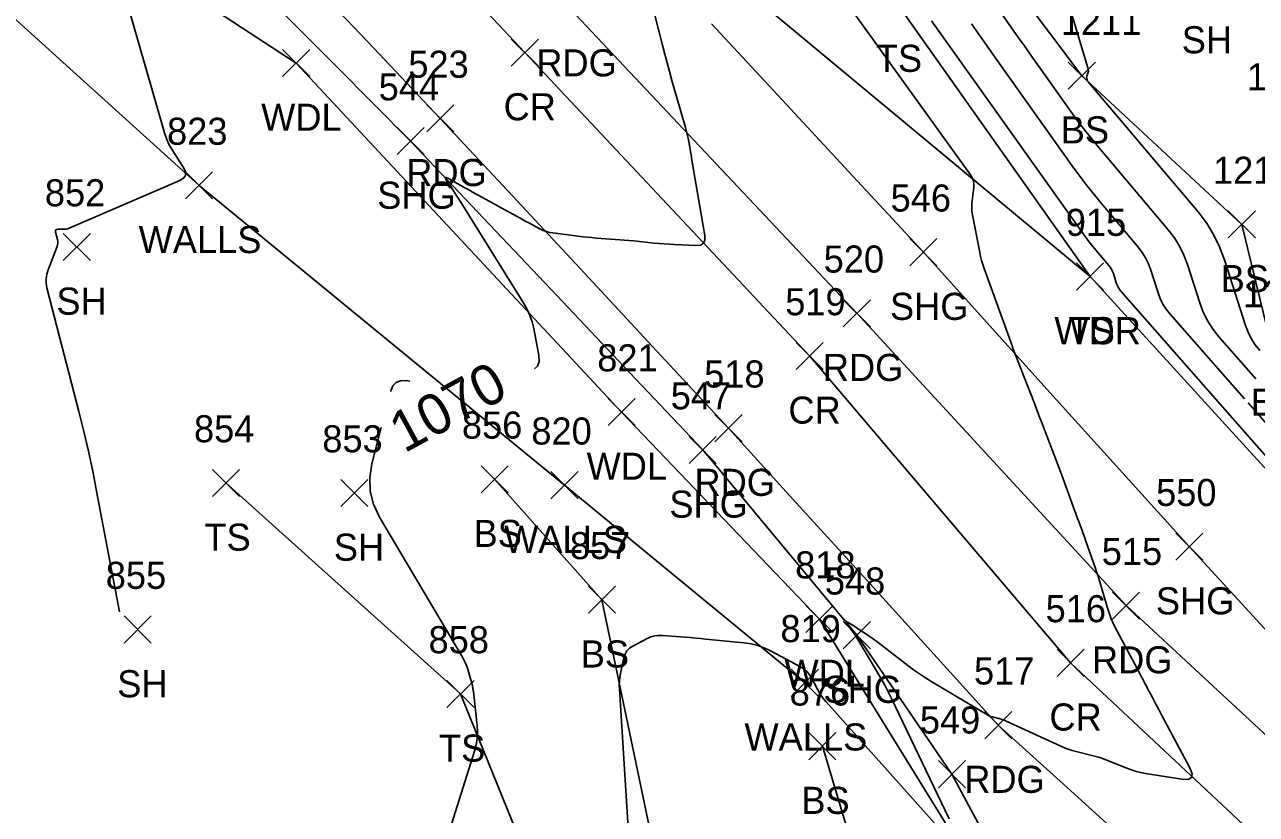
# Model space of a CAD drawing. Extents: x 1592612 to 1596497, y 111838 to 113741.
# Drawn here: x 1592719.3 to 1592810.3, y 113490.1 to 113548.4 of the extents above; entities that cross this region are included whole.
import ezdxf

# ---------------------------------------------------------------- set-up
doc = ezdxf.new("R2010")
doc.units = 0
for name, color, linetype in [('L_A', 7, 'Continuous'), ('L_I', 7, 'Continuous'), ('L_TIC', 7, 'Continuous'), ('LAWA', 7, 'Continuous'), ('LELB', 7, 'Continuous'), ('LSOGCMA', 7, 'Continuous'), ('LSOGCMA_T', 7, 'Continuous'), ('LSOGCMI', 7, 'Continuous'), ('LWS', 7, 'Continuous'), ('P_A', 7, 'Continuous'), ('P_I', 7, 'Continuous'), ('P_TIC', 7, 'Continuous'), ('PEU', 7, 'Continuous'), ('PRC', 7, 'Continuous'), ('PSU', 7, 'Continuous')]:
    doc.layers.add(name, color=color, linetype=linetype)

msp = doc.modelspace()

# ---------------------------------------------------------------- linework, layer by layer
at = {"layer": 'L_TIC'}
for points in [[(1592738.369, 113544.558), (1592740.369, 113546.558)], [(1592740.369, 113544.558), (1592738.369, 113546.558)], [(1592796.4, 113543.62), (1592798.4, 113545.62)], [(1592798.4, 113543.62), (1592796.4, 113545.62)], [(1592731.196, 113535.522), (1592733.196, 113537.522)], [(1592733.196, 113535.522), (1592731.196, 113537.522)], [(1592808.213, 113532.643), (1592810.213, 113534.643)], [(1592810.213, 113532.643), (1592808.213, 113534.643)], [(1592722.173, 113530.98), (1592724.173, 113532.98)], [(1592724.173, 113530.98), (1592722.173, 113532.98)], [(1592797.01, 113528.796), (1592799.01, 113530.796)], [(1592799.01, 113528.796), (1592797.01, 113530.796)], [(1592797.01, 113528.796), (1592799.01, 113530.796)], [(1592799.01, 113528.796), (1592797.01, 113530.796)], [(1592762.403, 113518.793), (1592764.403, 113520.793)], [(1592764.403, 113518.793), (1592762.403, 113520.793)], [(1592753.03, 113513.829), (1592755.03, 113515.829)], [(1592755.03, 113513.829), (1592753.03, 113515.829)], [(1592733.185, 113513.556), (1592735.185, 113515.556)], [(1592735.185, 113513.556), (1592733.185, 113515.556)], [(1592758.191, 113513.391), (1592760.191, 113515.391)], [(1592760.191, 113513.391), (1592758.191, 113515.391)], [(1592742.664, 113512.815), (1592744.664, 113514.815)], [(1592744.664, 113512.815), (1592742.664, 113514.815)], [(1592760.95, 113504.931), (1592762.95, 113506.931)], [(1592762.95, 113504.931), (1592760.95, 113506.931)], [(1592777.021, 113503.51), (1592779.021, 113505.51)], [(1592779.021, 113503.51), (1592777.021, 113505.51)], [(1592726.669, 113502.735), (1592728.669, 113504.735)], [(1592728.669, 113502.735), (1592726.669, 113504.735)], [(1592775.94, 113498.802), (1592777.94, 113500.802)], [(1592777.94, 113498.802), (1592775.94, 113500.802)], [(1592750.511, 113497.983), (1592752.511, 113499.983)], [(1592752.511, 113497.983), (1592750.511, 113499.983)], [(1592777.24, 113494.122), (1592779.24, 113496.122)], [(1592779.24, 113494.122), (1592777.24, 113496.122)]]:
    msp.add_lwpolyline(points, dxfattribs=at)
at = {"layer": 'LAWA'}
for points in [[(1592820.851, 113504.774), (1592798.01, 113529.796), (1592767.974, 113554.756), (1592744.7, 113575.871), (1592731.754, 113590.187), (1592719.52, 113602.847), (1592702.926, 113618.445), (1592691.78, 113628.612), (1592676.133, 113644.708)], [(1592820.49, 113445.204), (1592799.578, 113454.201), (1592791.672, 113482.437), (1592778.021, 113504.51), (1592763.403, 113519.793), (1592739.369, 113545.558), (1592709.175, 113565.248), (1592691.74, 113580.372), (1592683.654, 113590.995), (1592666.454, 113606.066), (1592652.114, 113621.499)]]:
    msp.add_lwpolyline(points, dxfattribs=at)
at = {"layer": 'LELB'}
for points in [[(1592701.588, 113659.774), (1592726.097, 113635.895), (1592737.453, 113625.119), (1592757.272, 113620.552), (1592765.525, 113604.487), (1592785.217, 113593.362), (1592785.143, 113579.955), (1592783.097, 113567.939), (1592785.828, 113560.008), (1592797.4, 113544.62), (1592809.213, 113533.643), (1592811.425, 113524.524), (1592820.841, 113522.69), (1592826.429, 113512.914)], [(1592798.011, 113529.796), (1592783.774, 113549.905), (1592769.456, 113556.017), (1592755.948, 113571.656), (1592745.631, 113578.976), (1592738.042, 113587.7)], [(1592734.185, 113514.556), (1592751.512, 113498.984), (1592760.463, 113476.916), (1592760.688, 113460.57), (1592763.141, 113446.688), (1592791.977, 113421.287)], [(1592754.03, 113514.829), (1592761.95, 113505.931), (1592768.508, 113474.511), (1592771.317, 113463.147), (1592774.096, 113455.731), (1592782.179, 113444.146), (1592797.263, 113432.126)], [(1592788.595, 113453.948), (1592784.52, 113474.069), (1592778.24, 113495.122)]]:
    msp.add_lwpolyline(points, dxfattribs=at)
at = {"layer": 'LSOGCMA'}
for points in [[(1592810.533, 113524.342), (1592810.2, 113524.762), (1592809.914, 113525.209), (1592809.677, 113525.684), (1592809.488, 113526.186), (1592807.935, 113531.03), (1592807.578, 113531.985), (1592807.133, 113532.892), (1592806.6, 113533.75), (1592805.981, 113534.56), (1592797.839, 113544.201), (1592797.819, 113544.228), (1592797.803, 113544.257), (1592797.791, 113544.288), (1592797.782, 113544.32), (1592797.757, 113544.455), (1592797.753, 113544.488), (1592797.753, 113544.521), (1592797.758, 113544.554), (1592797.767, 113544.587), (1592797.869, 113544.882), (1592797.884, 113544.942), (1592797.891, 113545.003), (1592797.887, 113545.063), (1592797.873, 113545.124), (1592795.23, 113553.926)], [(1592756.969, 113522.974), (1592757.197, 113523.169), (1592757.324, 113523.511), (1592757.303, 113523.958), (1592756.919, 113525.953), (1592756.801, 113526.443), (1592756.64, 113526.917), (1592756.435, 113527.373), (1592756.188, 113527.812), (1592751.475, 113535.355), (1592751.354, 113535.547), (1592751.232, 113535.738), (1592751.108, 113535.929), (1592750.984, 113536.119), (1592750.482, 113536.877), (1592750.397, 113537.029), (1592750.393, 113537.105), (1592750.47, 113537.107), (1592750.627, 113537.032), (1592751.885, 113536.322), (1592752.129, 113536.185), (1592752.374, 113536.048), (1592752.619, 113535.913), (1592752.865, 113535.778), (1592753.892, 113535.219), (1592754.117, 113535.096), (1592754.34, 113534.974), (1592754.564, 113534.85), (1592754.787, 113534.727), (1592755.703, 113534.218), (1592755.915, 113534.101), (1592756.128, 113533.985), (1592756.341, 113533.869), (1592756.554, 113533.755), (1592757.409, 113533.299), (1592757.626, 113533.195), (1592757.85, 113533.112), (1592758.08, 113533.051), (1592758.317, 113533.01), (1592760.193, 113532.775), (1592760.533, 113532.735), (1592760.874, 113532.699), (1592761.215, 113532.667), (1592761.556, 113532.64), (1592762.923, 113532.541), (1592763.265, 113532.515), (1592763.606, 113532.486), (1592763.948, 113532.456), (1592764.289, 113532.423), (1592765.822, 113532.269), (1592766.192, 113532.234), (1592766.561, 113532.204), (1592766.932, 113532.18), (1592767.302, 113532.16), (1592768.894, 113532.086), (1592769.226, 113532.118), (1592769.445, 113532.25), (1592769.551, 113532.484), (1592769.543, 113532.817), (1592768.606, 113538.382), (1592768.571, 113538.585), (1592768.536, 113538.788), (1592768.5, 113538.991), (1592768.463, 113539.194), (1592768.315, 113540.004), (1592768.276, 113540.206), (1592768.231, 113540.407), (1592768.182, 113540.607), (1592768.127, 113540.805), (1592767.128, 113544.279), (1592766.945, 113544.925), (1592766.767, 113545.572), (1592766.594, 113546.22), (1592766.426, 113546.87), (1592764.893, 113552.885)], [(1592746.351, 113521.304), (1592746.362, 113521.346), (1592746.518, 113521.722), (1592746.757, 113521.975), (1592747.08, 113522.104), (1592747.487, 113522.111), (1592747.765, 113522.076)], [(1592746.662, 113476.069), (1592752.554, 113494.753), (1592752.676, 113495.222), (1592752.748, 113495.697), (1592752.769, 113496.177), (1592752.739, 113496.661), (1592752.461, 113499.134), (1592752.431, 113499.357), (1592752.391, 113499.578), (1592752.34, 113499.797), (1592752.279, 113500.014), (1592752.013, 113500.877), (1592751.941, 113501.09), (1592751.857, 113501.298), (1592751.76, 113501.5), (1592751.651, 113501.697), (1592745.525, 113512.039), (1592745.079, 113512.979), (1592744.837, 113513.948), (1592744.8, 113514.946), (1592744.968, 113515.973), (1592745.661, 113518.643)]]:
    msp.add_lwpolyline(points, dxfattribs=at)
at = {"layer": 'LSOGCMI'}
for points in [[(1592810.254, 113522.233), (1592807.547, 113525.315), (1592807.089, 113525.893), (1592806.696, 113526.509), (1592806.37, 113527.162), (1592806.109, 113527.853), (1592805.2, 113530.69), (1592804.941, 113531.382), (1592804.619, 113532.038), (1592804.233, 113532.66), (1592803.784, 113533.247), (1592798.644, 113539.333), (1592798.111, 113539.978), (1592797.592, 113540.632), (1592797.087, 113541.298), (1592796.595, 113541.973), (1592794.656, 113544.698), (1592794.172, 113545.38), (1592793.689, 113546.062), (1592793.207, 113546.746), (1592792.727, 113547.43), (1592785.78, 113557.351)], [(1592726.316, 113505.046), (1592724.636, 113513.939), (1592724.343, 113515.419), (1592724.027, 113516.893), (1592723.687, 113518.361), (1592723.322, 113519.825), (1592720.966, 113528.959), (1592720.905, 113529.298), (1592720.898, 113529.634), (1592720.945, 113529.967), (1592721.047, 113530.296), (1592721.718, 113532.016), (1592721.756, 113532.14), (1592721.774, 113532.266), (1592721.771, 113532.393), (1592721.747, 113532.521), (1592721.597, 113533.082), (1592721.586, 113533.174), (1592721.609, 113533.239), (1592721.666, 113533.277), (1592721.758, 113533.288), (1592722.191, 113533.281), (1592722.299, 113533.285), (1592722.404, 113533.3), (1592722.507, 113533.326), (1592722.607, 113533.364), (1592730.784, 113536.883), (1592731.059, 113537.051), (1592731.198, 113537.261), (1592731.201, 113537.513), (1592731.067, 113537.807), (1592730.26, 113539.064), (1592730.07, 113539.384), (1592729.905, 113539.715), (1592729.765, 113540.058), (1592729.65, 113540.411), (1592726.376, 113551.8)], [(1592779.148, 113551.224), (1592789.18, 113537.302), (1592789.309, 113537.086), (1592789.392, 113536.858), (1592789.43, 113536.618), (1592789.423, 113536.367), (1592789.285, 113535.184), (1592789.27, 113535.003), (1592789.27, 113534.823), (1592789.283, 113534.643), (1592789.31, 113534.464), (1592789.859, 113531.574), (1592789.923, 113531.273), (1592789.998, 113530.975), (1592790.085, 113530.68), (1592790.183, 113530.388), (1592792.217, 113524.746), (1592792.33, 113524.434), (1592792.447, 113524.123), (1592792.565, 113523.814), (1592792.687, 113523.505), (1592793.587, 113521.238), (1592793.653, 113521.069), (1592793.719, 113520.899), (1592793.784, 113520.729), (1592793.847, 113520.559), (1592794.1, 113519.876), (1592794.164, 113519.705), (1592794.228, 113519.535), (1592794.293, 113519.364), (1592794.358, 113519.195), (1592795.335, 113516.684), (1592795.51, 113516.231), (1592795.682, 113515.776), (1592795.851, 113515.32), (1592796.018, 113514.863), (1592796.879, 113512.476), (1592796.944, 113512.297), (1592797.01, 113512.119), (1592797.076, 113511.94), (1592797.144, 113511.762), (1592797.415, 113511.05), (1592797.482, 113510.872), (1592797.548, 113510.694), (1592797.613, 113510.515), (1592797.676, 113510.335), (1592798.408, 113508.252), (1592798.493, 113508.004), (1592798.575, 113507.755), (1592798.652, 113507.505), (1592798.726, 113507.254), (1592799.06, 113506.082), (1592799.11, 113505.912), (1592799.161, 113505.743), (1592799.213, 113505.574), (1592799.267, 113505.406), (1592799.487, 113504.734), (1592799.545, 113504.567), (1592799.61, 113504.404), (1592799.683, 113504.243), (1592799.762, 113504.085), (1592800.627, 113502.461), (1592800.799, 113502.139), (1592800.97, 113501.816), (1592801.142, 113501.493), (1592801.313, 113501.17), (1592802.378, 113499.159), (1592802.613, 113498.716), (1592802.848, 113498.273), (1592803.084, 113497.831), (1592803.319, 113497.389), (1592805.384, 113493.523), (1592805.549, 113493.091), (1592805.506, 113492.808), (1592805.253, 113492.674), (1592804.791, 113492.689), (1592802.101, 113493.11), (1592801.749, 113493.176), (1592801.402, 113493.261), (1592801.061, 113493.366), (1592800.724, 113493.49), (1592799.282, 113494.072), (1592799.001, 113494.179), (1592798.717, 113494.276), (1592798.43, 113494.364), (1592798.14, 113494.441), (1592796.972, 113494.731), (1592796.683, 113494.81), (1592796.398, 113494.902), (1592796.117, 113495.008), (1592795.842, 113495.127), (1592791.756, 113497.003), (1592791.707, 113497.024), (1592791.658, 113497.044), (1592791.608, 113497.062), (1592791.558, 113497.078), (1592791.355, 113497.139), (1592791.304, 113497.154), (1592791.253, 113497.169), (1592791.202, 113497.182), (1592791.15, 113497.195), (1592790.799, 113497.278), (1592790.724, 113497.299), (1592790.652, 113497.325), (1592790.582, 113497.357), (1592790.514, 113497.394), (1592786.324, 113499.877), (1592785.864, 113500.159), (1592785.414, 113500.455), (1592784.973, 113500.764), (1592784.541, 113501.087), (1592782.25, 113502.854), (1592782.113, 113502.958), (1592781.975, 113503.059), (1592781.835, 113503.157), (1592781.693, 113503.254), (1592781.08, 113503.66), (1592780.957, 113503.741), (1592780.834, 113503.821), (1592780.711, 113503.9), (1592780.586, 113503.978), (1592780.089, 113504.29), (1592779.991, 113504.344), (1592779.946, 113504.348), (1592779.953, 113504.303), (1592780.013, 113504.209), (1592780.419, 113503.655), (1592780.514, 113503.522), (1592780.606, 113503.387), (1592780.694, 113503.249), (1592780.78, 113503.11), (1592782.298, 113500.571), (1592782.574, 113500.098), (1592782.838, 113499.619), (1592783.092, 113499.135), (1592783.334, 113498.644), (1592787.599, 113489.76)], [(1592820.17, 113506.097), (1592800.29, 113528.724), (1592800.181, 113528.863), (1592800.087, 113529.01), (1592800.009, 113529.166), (1592799.946, 113529.331), (1592799.729, 113530.009), (1592799.667, 113530.175), (1592799.59, 113530.332), (1592799.498, 113530.48), (1592799.391, 113530.621), (1592798.333, 113531.873), (1592798.121, 113532.129), (1592797.915, 113532.389), (1592797.714, 113532.654), (1592797.518, 113532.923), (1592786.547, 113548.337), (1592786.305, 113548.677)], [(1592809.409, 113520.77), (1592803.919, 113527.02), (1592803.635, 113527.378), (1592803.391, 113527.759), (1592803.189, 113528.164), (1592803.028, 113528.592), (1592802.464, 113530.35), (1592802.304, 113530.778), (1592802.104, 113531.185), (1592801.865, 113531.57), (1592801.587, 113531.934), (1592798.847, 113535.179), (1592798.298, 113535.843), (1592797.763, 113536.518), (1592797.242, 113537.204), (1592796.735, 113537.9), (1592791.164, 113545.728), (1592790.52, 113546.634), (1592789.878, 113547.541), (1592789.238, 113548.45)], [(1592817.143, 113511.967), (1592809.679, 113520.463)], [(1592786.745, 113489.191), (1592778.513, 113498.4), (1592778.34, 113498.605), (1592778.181, 113498.82), (1592778.035, 113499.044), (1592777.902, 113499.276), (1592777.398, 113500.227), (1592777.258, 113500.451), (1592777.091, 113500.646), (1592776.895, 113500.814), (1592776.671, 113500.954), (1592774.403, 113502.155), (1592773.939, 113502.373), (1592773.46, 113502.544), (1592772.967, 113502.667), (1592772.459, 113502.743), (1592769.612, 113503.03), (1592769.235, 113503.068), (1592768.858, 113503.103), (1592768.481, 113503.136), (1592768.103, 113503.168), (1592766.439, 113503.302), (1592766.143, 113503.306), (1592765.855, 113503.269), (1592765.576, 113503.191), (1592765.305, 113503.071), (1592764.229, 113502.507), (1592763.992, 113502.351), (1592763.805, 113502.157), (1592763.667, 113501.924), (1592763.58, 113501.654), (1592763.33, 113500.497), (1592763.278, 113500.207), (1592763.246, 113499.915), (1592763.234, 113499.622), (1592763.242, 113499.328), (1592764.612, 113477.686)]]:
    msp.add_lwpolyline(points, dxfattribs=at)
at = {"layer": 'LWS'}
msp.add_lwpolyline([(1592776.94, 113499.802), (1592759.191, 113514.391), (1592732.196, 113536.522), (1592707.136, 113559.182), (1592694.649, 113568.778), (1592678.365, 113587.138), (1592659.477, 113602.479)], dxfattribs=at)
at = {"layer": 'P_TIC'}
for points in [[(1592755.259, 113545.33), (1592757.259, 113547.33)], [(1592757.259, 113545.33), (1592755.259, 113547.33)], [(1592749.018, 113540.472), (1592751.018, 113542.472)], [(1592751.018, 113540.472), (1592749.018, 113542.472)], [(1592746.826, 113538.8), (1592748.826, 113540.8)], [(1592748.826, 113538.8), (1592746.826, 113540.8)], [(1592784.693, 113530.593), (1592786.693, 113532.593)], [(1592786.693, 113530.593), (1592784.693, 113532.593)], [(1592779.779, 113526.086), (1592781.779, 113528.086)], [(1592781.779, 113526.086), (1592779.779, 113528.086)], [(1592776.295, 113522.934), (1592778.295, 113524.934)], [(1592778.295, 113522.934), (1592776.295, 113524.934)], [(1592770.302, 113517.6), (1592772.302, 113519.6)], [(1592772.302, 113517.6), (1592770.302, 113519.6)], [(1592768.397, 113515.992), (1592770.397, 113517.992)], [(1592770.397, 113515.992), (1592768.397, 113517.992)], [(1592804.331, 113508.853), (1592806.331, 113510.853)], [(1592806.331, 113508.853), (1592804.331, 113510.853)], [(1592799.662, 113504.499), (1592801.662, 113506.499)], [(1592801.662, 113504.499), (1592799.662, 113506.499)], [(1592779.779, 113502.319), (1592781.779, 113504.319)], [(1592781.779, 113502.319), (1592779.779, 113504.319)], [(1592795.573, 113500.275), (1592797.573, 113502.275)], [(1592797.573, 113500.275), (1592795.573, 113502.275)], [(1592790.228, 113495.676), (1592792.228, 113497.676)], [(1592792.228, 113495.676), (1592790.228, 113497.676)], [(1592786.807, 113492.055), (1592788.807, 113494.055)], [(1592788.807, 113492.055), (1592786.807, 113494.055)]]:
    msp.add_lwpolyline(points, dxfattribs=at)
at = {"layer": 'PEU'}
for points in [[(1592852.273, 113463.849), (1592836.279, 113474.056), (1592819.972, 113487.621), (1592800.662, 113505.499), (1592780.779, 113527.086), (1592759.62, 113549.571), (1592738.37, 113572.943), (1592716.192, 113596.277), (1592693.964, 113619.189), (1592672.676, 113639.672)], [(1592849.263, 113454.813), (1592844.314, 113457.324), (1592839.36, 113459.838), (1592834.406, 113462.353), (1592829.452, 113464.867), (1592824.976, 113468.213), (1592820.499, 113471.559), (1592816.022, 113474.905), (1592811.546, 113478.25), (1592806.466, 113482.857), (1592801.387, 113487.463), (1592796.307, 113492.07), (1592791.228, 113496.676), (1592786.246, 113502.157), (1592781.265, 113507.638), (1592776.283, 113513.119), (1592771.302, 113518.6), (1592765.981, 113524.318), (1592760.66, 113530.036), (1592755.339, 113535.754), (1592750.018, 113541.472), (1592744.662, 113547.12), (1592739.305, 113552.768)]]:
    msp.add_lwpolyline(points, dxfattribs=at)
at = {"layer": 'PRC'}
msp.add_lwpolyline([(1592851.008, 113460.149), (1592833.097, 113469.523), (1592815.857, 113483.202), (1592796.573, 113501.275), (1592777.295, 113523.934), (1592756.259, 113546.33), (1592734.615, 113569.346), (1592712.839, 113593.061), (1592690.495, 113615.302), (1592669.477, 113636.459)], dxfattribs=at)
at = {"layer": 'PSU'}
for points in [[(1592736.914, 113550.763), (1592742.37, 113545.281), (1592747.826, 113539.8), (1592753.219, 113534.098), (1592758.612, 113528.396), (1592764.004, 113522.694), (1592769.397, 113516.992), (1592775.088, 113510.156), (1592780.779, 113503.319), (1592784.293, 113498.187), (1592787.807, 113493.055), (1592790.997, 113487.112), (1592794.187, 113481.168), (1592797.377, 113475.225), (1592800.567, 113469.281), (1592805.227, 113460.599), (1592810.348, 113452.325), (1592818.506, 113453.604), (1592826.665, 113454.883), (1592832.198, 113454.513), (1592837.731, 113454.142), (1592843.264, 113453.772), (1592848.786, 113453.402)], [(1592770.049, 113548.457), (1592775.263, 113542.835), (1592780.478, 113537.214), (1592785.693, 113531.593), (1592790.602, 113526.158), (1592795.512, 113520.723), (1592800.422, 113515.288), (1592805.331, 113509.853), (1592809.758, 113505.035), (1592814.184, 113500.218), (1592818.611, 113495.4), (1592823.037, 113490.583), (1592826.914, 113487.218), (1592830.791, 113483.853), (1592834.668, 113480.488), (1592838.545, 113477.123), (1592845.634, 113471.053), (1592852.707, 113464.996)]]:
    msp.add_lwpolyline(points, dxfattribs=at)

# ---------------------------------------------------------------- texts
at = {"layer": 'L_A'}
for s, p in [('SH', (1592804.776, 113546.276)), ('TS', (1592782.183, 113544.905)), ('WDL', (1592736.787, 113540.558)), ('BS', (1592795.841, 113539.62)), ('WALLS', (1592727.739, 113531.522)), ('BS', (1592807.653, 113528.643)), ('SH', (1592721.661, 113526.98)), ('WDR', (1592795.373, 113524.796)), ('TS', (1592796.42, 113524.796)), ('BS', (1592809.866, 113519.523)), ('WDL', (1592760.82, 113514.793)), ('TS', (1592732.594, 113509.556)), ('BS', (1592752.471, 113509.829)), ('WALLS', (1592754.734, 113509.391)), ('SH', (1592742.152, 113508.815)), ('BS', (1592760.391, 113500.931)), ('WDL', (1592775.438, 113499.51)), ('SH', (1592726.157, 113498.735)), ('WALLS', (1592772.483, 113494.802)), ('TS', (1592749.921, 113493.983)), ('BS', (1592776.681, 113490.122))]:
    msp.add_text(s, height=2, dxfattribs=at).set_placement(p)
at = {"layer": 'L_I'}
for s, p in [('1211', (1592795.841, 113547.62)), ('1213', (1592809.578, 113543.535)), ('823', (1592729.834, 113539.522)), ('1214', (1592807.087, 113536.643)), ('852', (1592720.811, 113534.98)), ('915', (1592796.215, 113532.796)), ('915', (1592796.215, 113532.796)), ('1215', (1592809.299, 113527.523)), ('821', (1592761.608, 113522.793)), ('854', (1592731.823, 113517.556)), ('856', (1592751.612, 113517.829)), ('853', (1592741.302, 113516.815)), ('820', (1592756.742, 113517.391)), ('857', (1592759.588, 113508.931)), ('818', (1592776.225, 113507.51)), ('855', (1592725.307, 113506.735)), ('858', (1592749.149, 113501.983)), ('819', (1592775.137, 113502.802)), ('876', (1592775.823, 113498.122))]:
    msp.add_text(s, height=2, dxfattribs=at).set_placement(p)
at = {"layer": 'LSOGCMA_T'}
msp.add_text('1070', height=3, rotation=28.66052, dxfattribs=at).set_placement((1592747.356, 113516.724))
at = {"layer": 'P_A'}
for s, p in [('RDG', (1592757.108, 113544.571)), ('CR', (1592754.692, 113541.33)), ('RDG', (1592747.506, 113536.472)), ('SHG', (1592745.361, 113534.8)), ('SHG', (1592783.228, 113526.593)), ('RDG', (1592778.267, 113522.086)), ('CR', (1592775.728, 113518.934)), ('RDG', (1592768.79, 113513.6)), ('SHG', (1592766.933, 113511.992)), ('SHG', (1592802.867, 113504.853)), ('RDG', (1592798.151, 113500.499)), ('SHG', (1592778.314, 113498.319)), ('CR', (1592795.006, 113496.275)), ('RDG', (1592788.716, 113491.676))]:
    msp.add_text(s, height=2, dxfattribs=at).set_placement(p)
at = {"layer": 'P_I'}
for s, p in [('523', (1592747.656, 113544.472)), ('544', (1592745.464, 113542.8)), ('546', (1592783.275, 113534.593)), ('520', (1592778.33, 113530.086)), ('519', (1592775.492, 113526.934)), ('518', (1592769.507, 113521.6)), ('547', (1592767.035, 113519.992)), ('550', (1592802.883, 113512.853)), ('515', (1592798.867, 113508.499)), ('548', (1592778.416, 113506.319)), ('516', (1592794.723, 113504.275)), ('517', (1592789.433, 113499.676)), ('549', (1592785.437, 113496.055))]:
    msp.add_text(s, height=2, dxfattribs=at).set_placement(p)

doc.saveas('drawing.dxf')
